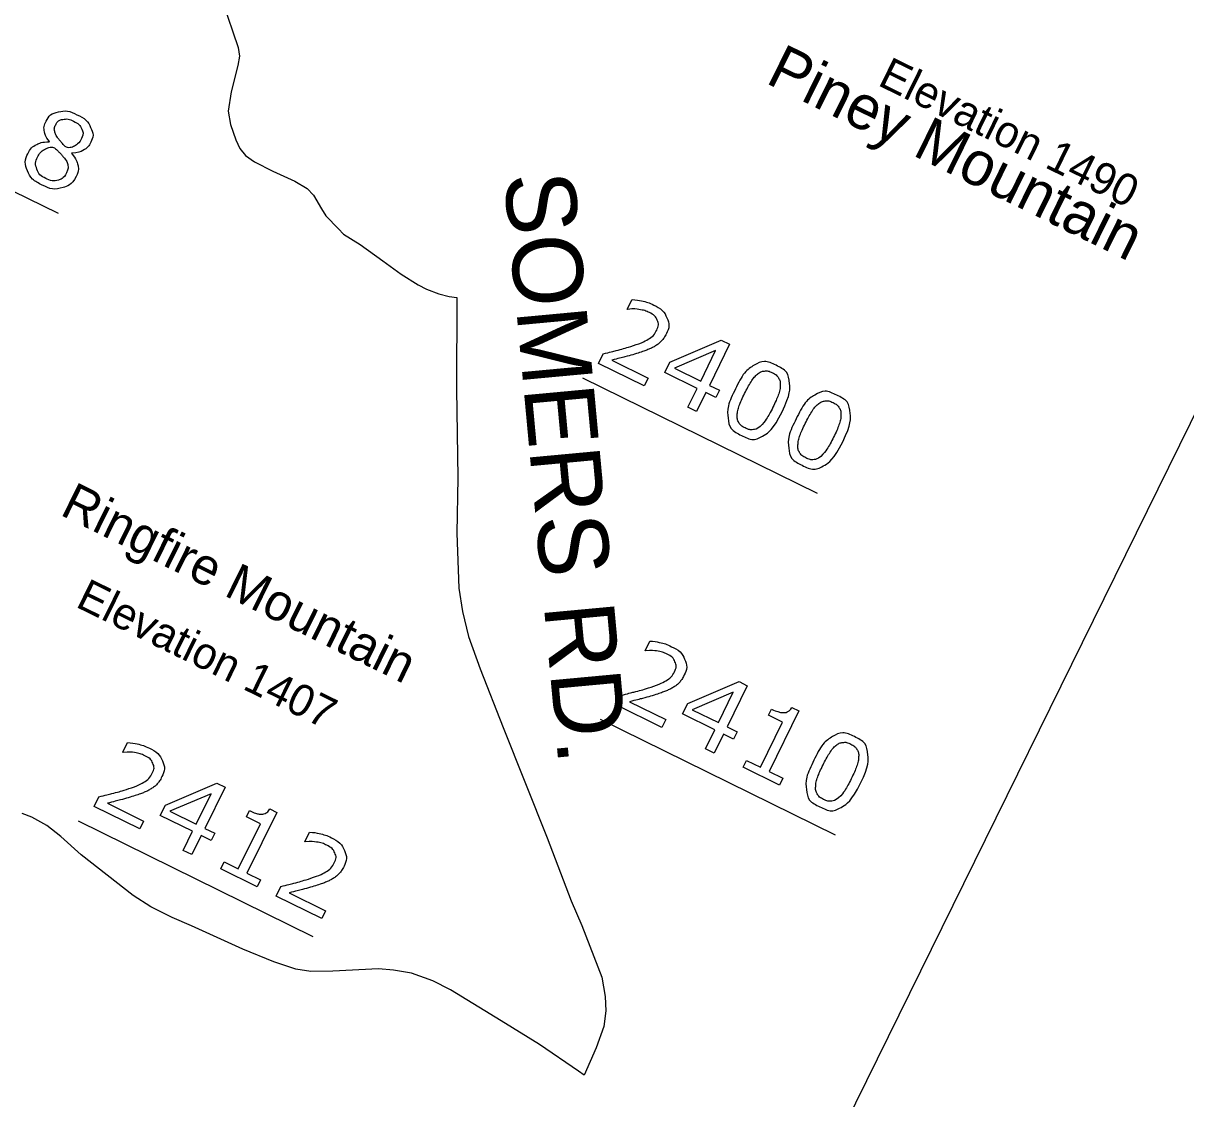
# Model space of a CAD drawing. Extents: x 1428128 to 1430390, y 857947 to 859822.
# Drawn here: x 1429189.4 to 1429305.6, y 859217.9 to 859325.3 of the extents above; entities that cross this region are included whole.
import ezdxf

# ---------------------------------------------------------------- set-up
doc = ezdxf.new("R2010")
doc.units = 0
doc.layers.add('Old_Level_1', color=7, linetype='Continuous')
doc.layers.add('Sheet Title CELL', color=7, linetype='Continuous')

msp = doc.modelspace()

# ---------------------------------------------------------------- linework, layer by layer
at = {"layer": 'Old_Level_1'}
for p, q in [((1429169.37, 859317.89), (1429192.89, 859306.32)), ((1429245.28, 859289.88), (1429268.74, 859278.34)), ((1429247.05, 859255.76), (1429270.52, 859244.22)), ((1429194.88, 859245.62), (1429218.35, 859234.07))]:
    msp.add_line(p, q, dxfattribs=at)
for points in [[(1429192, 859313.45), (1429192.02, 859313.48)], [(1429194.23, 859312.34), (1429194.22, 859312.31)], [(1429249.81, 859296.72), (1429249.76, 859296.75), (1429250.23, 859297.69)], [(1429258.6, 859287.91), (1429257.6, 859288.41), (1429256.67, 859286.51), (1429255.8, 859286.94), (1429256.73, 859288.83), (1429253.51, 859290.42), (1429254.02, 859291.46), (1429259.15, 859293.65), (1429259.98, 859293.24), (1429257.96, 859289.13), (1429258.96, 859288.64), (1429258.6, 859287.91)], [(1429251.45, 859289.08), (1429246.89, 859291.32), (1429247.36, 859292.27)], [(1429257.09, 859289.56), (1429258.58, 859292.6), (1429254.48, 859290.84), (1429257.09, 859289.56)], [(1429248.21, 859291.64), (1429251.83, 859289.86), (1429251.45, 859289.08)], [(1429251.58, 859262.6), (1429251.53, 859262.62), (1429252, 859263.57)], [(1429260.37, 859253.79), (1429259.37, 859254.29), (1429258.44, 859252.39), (1429257.57, 859252.82), (1429258.5, 859254.71), (1429255.28, 859256.3), (1429255.79, 859257.34), (1429260.92, 859259.53), (1429261.75, 859259.12), (1429259.73, 859255.01), (1429260.73, 859254.52), (1429260.37, 859253.79)], [(1429253.22, 859254.96), (1429248.66, 859257.2), (1429249.13, 859258.15)], [(1429258.86, 859255.44), (1429260.35, 859258.48), (1429256.25, 859256.72), (1429258.86, 859255.44)], [(1429249.98, 859257.52), (1429253.6, 859255.74), (1429253.22, 859254.96)], [(1429266.21, 859256.95), (1429266.91, 859256.61), (1429263.93, 859250.54), (1429265.3, 859249.87), (1429264.96, 859249.18)], [(1429264.96, 859249.18), (1429261.32, 859250.97), (1429261.66, 859251.66), (1429263.06, 859250.97), (1429265.28, 859255.48), (1429263.88, 859256.17), (1429264.18, 859256.78)], [(1429199.4, 859252.46), (1429199.36, 859252.48), (1429199.83, 859253.43)], [(1429208.19, 859243.65), (1429207.19, 859244.14), (1429206.26, 859242.24), (1429205.39, 859242.67), (1429206.33, 859244.57), (1429203.1, 859246.15), (1429203.61, 859247.19), (1429208.74, 859249.38), (1429209.57, 859248.97), (1429207.55, 859244.86), (1429208.55, 859244.37), (1429208.19, 859243.65)], [(1429201.05, 859244.81), (1429196.49, 859247.05), (1429196.95, 859248.01)], [(1429206.68, 859245.29), (1429208.18, 859248.33), (1429204.07, 859246.58), (1429206.68, 859245.29)], [(1429197.81, 859247.37), (1429201.43, 859245.59), (1429201.05, 859244.81)], [(1429212.79, 859239.03), (1429209.14, 859240.83), (1429209.48, 859241.51), (1429210.88, 859240.82), (1429213.1, 859245.33), (1429211.7, 859246.02), (1429212, 859246.64)], [(1429214.03, 859246.81), (1429214.74, 859246.46), (1429211.75, 859240.4), (1429213.12, 859239.72), (1429212.79, 859239.03)], [(1429217.59, 859243.51), (1429217.55, 859243.53), (1429218.01, 859244.48)], [(1429219.23, 859235.86), (1429214.67, 859238.1), (1429215.14, 859239.06)], [(1429215.99, 859238.42), (1429219.62, 859236.64), (1429219.23, 859235.86)]]:
    msp.add_lwpolyline(points, dxfattribs=at)
for points in [[(1429192.02, 859313.48), (1429191.61, 859314.03), (1429191.52, 859314.5), (1429191.43, 859314.98), (1429191.69, 859315.49), (1429192.06, 859316.25), (1429192.93, 859316.45), (1429193.81, 859316.65), (1429194.77, 859316.17), (1429195.78, 859315.68), (1429196.14, 859314.9), (1429196.5, 859314.12), (1429196.14, 859313.37), (1429195.91, 859312.92), (1429195.41, 859312.62), (1429194.91, 859312.32), (1429194.23, 859312.34)], [(1429195.24, 859313.8), (1429195.48, 859314.29), (1429195.25, 859314.76), (1429195.02, 859315.23), (1429194.44, 859315.51), (1429193.87, 859315.79), (1429193.37, 859315.7), (1429192.87, 859315.61), (1429192.64, 859315.15), (1429192.48, 859314.82), (1429192.55, 859314.5), (1429192.62, 859314.17), (1429192.9, 859313.8), (1429193.02, 859313.64), (1429193.27, 859313.35), (1429193.52, 859313.06), (1429193.78, 859312.83), (1429194.38, 859312.91), (1429194.71, 859313.15), (1429195.04, 859313.38), (1429195.24, 859313.8)], [(1429194.7, 859309.99), (1429194.27, 859309.12), (1429193.3, 859308.87), (1429192.34, 859308.63), (1429191.31, 859309.14), (1429190.21, 859309.68), (1429189.84, 859310.56), (1429189.47, 859311.44), (1429189.9, 859312.33), (1429190.18, 859312.89), (1429190.73, 859313.18), (1429191.28, 859313.47), (1429192, 859313.45)], [(1429193.73, 859310.36), (1429193.93, 859310.78), (1429193.87, 859311.12), (1429193.81, 859311.46), (1429193.4, 859311.97), (1429193.24, 859312.18), (1429193.03, 859312.39), (1429192.82, 859312.6), (1429192.47, 859312.96), (1429191.96, 859312.94), (1429191.52, 859312.68), (1429191.09, 859312.42), (1429190.85, 859311.94), (1429190.55, 859311.33), (1429190.78, 859310.73), (1429191, 859310.12), (1429191.65, 859309.81), (1429192.31, 859309.48), (1429192.87, 859309.63), (1429193.44, 859309.77), (1429193.73, 859310.36)], [(1429194.22, 859312.31), (1429194.72, 859311.73), (1429194.86, 859311.17), (1429195, 859310.6), (1429194.7, 859309.99)], [(1429250.23, 859297.69), (1429250.63, 859297.69), (1429251.23, 859297.56), (1429251.83, 859297.43), (1429252.33, 859297.18), (1429253.37, 859296.67), (1429253.71, 859295.88), (1429254.05, 859295.09), (1429253.63, 859294.24), (1429253.45, 859293.86), (1429253.18, 859293.57), (1429252.92, 859293.29), (1429252.59, 859293.08), (1429252.27, 859292.89), (1429251.9, 859292.74), (1429251.53, 859292.58), (1429251.03, 859292.42), (1429250.31, 859292.18), (1429249.58, 859291.99), (1429248.84, 859291.8), (1429248.21, 859291.64)], [(1429247.36, 859292.27), (1429248.03, 859292.45), (1429248.71, 859292.62), (1429249.39, 859292.79), (1429250, 859292.99), (1429251.28, 859293.4), (1429251.85, 859293.74), (1429252.41, 859294.07), (1429252.7, 859294.65), (1429252.95, 859295.17), (1429252.75, 859295.64), (1429252.55, 859296.1), (1429251.93, 859296.41), (1429251.52, 859296.61), (1429250.97, 859296.7), (1429250.41, 859296.8), (1429249.81, 859296.72)], [(1429265.22, 859286.49), (1429264.33, 859284.67), (1429263.34, 859284.1), (1429262.36, 859283.53), (1429261.17, 859284.12), (1429259.96, 859284.72), (1429259.82, 859285.85), (1429259.69, 859286.98), (1429260.56, 859288.77), (1429261.45, 859290.56), (1429262.44, 859291.14), (1429263.42, 859291.72), (1429264.62, 859291.13), (1429265.83, 859290.54), (1429265.96, 859289.39), (1429266.09, 859288.25), (1429265.22, 859286.49)], [(1429263.02, 859285.02), (1429263.36, 859285.31), (1429263.66, 859285.77), (1429263.96, 859286.24), (1429264.3, 859286.94), (1429264.64, 859287.63), (1429264.84, 859288.16), (1429265.03, 859288.7), (1429265.04, 859289.13), (1429265.05, 859289.55), (1429264.87, 859289.87), (1429264.68, 859290.18), (1429264.25, 859290.39), (1429263.83, 859290.6), (1429263.46, 859290.56), (1429263.1, 859290.52), (1429262.76, 859290.24), (1429262.44, 859289.98), (1429262.12, 859289.47), (1429261.8, 859288.96), (1429261.48, 859288.32), (1429261.13, 859287.61), (1429260.95, 859287.11), (1429260.77, 859286.61), (1429260.74, 859286.15), (1429260.72, 859285.73), (1429260.9, 859285.41), (1429261.08, 859285.09), (1429261.54, 859284.87), (1429261.96, 859284.66), (1429262.33, 859284.7), (1429262.69, 859284.74), (1429263.02, 859285.02)], [(1429271.29, 859283.5), (1429270.39, 859281.69), (1429269.41, 859281.12), (1429268.42, 859280.55), (1429267.23, 859281.14), (1429266.02, 859281.73), (1429265.89, 859282.87), (1429265.75, 859284), (1429266.63, 859285.78), (1429267.51, 859287.58), (1429268.5, 859288.16), (1429269.49, 859288.74), (1429270.68, 859288.15), (1429271.89, 859287.56), (1429272.02, 859286.41), (1429272.15, 859285.26), (1429271.29, 859283.5)], [(1429269.09, 859282.03), (1429269.42, 859282.32), (1429269.72, 859282.79), (1429270.02, 859283.26), (1429270.37, 859283.95), (1429270.71, 859284.64), (1429270.9, 859285.18), (1429271.09, 859285.71), (1429271.1, 859286.14), (1429271.12, 859286.57), (1429270.93, 859286.88), (1429270.74, 859287.19), (1429270.31, 859287.4), (1429269.89, 859287.61), (1429269.53, 859287.57), (1429269.16, 859287.53), (1429268.82, 859287.26), (1429268.5, 859287), (1429268.18, 859286.49), (1429267.86, 859285.98), (1429267.55, 859285.33), (1429267.2, 859284.63), (1429267.01, 859284.13), (1429266.83, 859283.63), (1429266.81, 859283.17), (1429266.78, 859282.75), (1429266.96, 859282.43), (1429267.15, 859282.11), (1429267.6, 859281.88), (1429268.02, 859281.67), (1429268.39, 859281.71), (1429268.76, 859281.75), (1429269.09, 859282.03)], [(1429249.13, 859258.15), (1429249.81, 859258.33), (1429250.48, 859258.5), (1429251.16, 859258.67), (1429251.77, 859258.87), (1429253.05, 859259.28), (1429253.62, 859259.62), (1429254.18, 859259.95), (1429254.47, 859260.53), (1429254.72, 859261.05), (1429254.52, 859261.52), (1429254.32, 859261.98), (1429253.7, 859262.29), (1429253.29, 859262.49), (1429252.74, 859262.58), (1429252.18, 859262.67), (1429251.58, 859262.6)], [(1429252, 859263.57), (1429252.4, 859263.57), (1429253, 859263.44), (1429253.6, 859263.31), (1429254.1, 859263.06), (1429255.14, 859262.55), (1429255.48, 859261.76), (1429255.83, 859260.97), (1429255.41, 859260.12), (1429255.22, 859259.73), (1429254.96, 859259.45), (1429254.7, 859259.17), (1429254.36, 859258.96), (1429254.04, 859258.77), (1429253.67, 859258.61), (1429253.3, 859258.46), (1429252.8, 859258.3), (1429252.08, 859258.06), (1429251.35, 859257.87), (1429250.62, 859257.68), (1429249.98, 859257.52)], [(1429264.18, 859256.78), (1429264.46, 859256.64), (1429264.81, 859256.53), (1429265.16, 859256.42), (1429265.37, 859256.43), (1429265.64, 859256.44), (1429265.84, 859256.55), (1429266.05, 859256.67), (1429266.21, 859256.95)], [(1429199.83, 859253.43), (1429200.22, 859253.43), (1429200.83, 859253.29), (1429201.43, 859253.16), (1429201.93, 859252.91), (1429202.96, 859252.4), (1429203.31, 859251.61), (1429203.65, 859250.83), (1429203.23, 859249.97), (1429203.04, 859249.59), (1429202.78, 859249.3), (1429202.52, 859249.02), (1429202.18, 859248.82), (1429201.87, 859248.62), (1429201.5, 859248.47), (1429201.13, 859248.31), (1429200.63, 859248.15), (1429199.91, 859247.92), (1429199.17, 859247.72), (1429198.44, 859247.53), (1429197.81, 859247.37)], [(1429273.06, 859249.38), (1429272.16, 859247.57), (1429271.18, 859247), (1429270.19, 859246.43), (1429269, 859247.01), (1429267.79, 859247.61), (1429267.66, 859248.74), (1429267.52, 859249.88), (1429268.4, 859251.66), (1429269.28, 859253.46), (1429270.27, 859254.04), (1429271.26, 859254.62), (1429272.45, 859254.03), (1429273.66, 859253.43), (1429273.79, 859252.29), (1429273.92, 859251.14), (1429273.06, 859249.38)], [(1429270.86, 859247.91), (1429271.2, 859248.2), (1429271.5, 859248.67), (1429271.8, 859249.14), (1429272.14, 859249.83), (1429272.48, 859250.52), (1429272.67, 859251.06), (1429272.86, 859251.59), (1429272.87, 859252.02), (1429272.89, 859252.45), (1429272.7, 859252.76), (1429272.51, 859253.07), (1429272.09, 859253.28), (1429271.66, 859253.49), (1429271.3, 859253.45), (1429270.93, 859253.41), (1429270.59, 859253.13), (1429270.28, 859252.88), (1429269.95, 859252.36), (1429269.63, 859251.85), (1429269.32, 859251.21), (1429268.97, 859250.51), (1429268.78, 859250.01), (1429268.6, 859249.51), (1429268.58, 859249.05), (1429268.55, 859248.62), (1429268.74, 859248.3), (1429268.92, 859247.98), (1429269.37, 859247.76), (1429269.79, 859247.55), (1429270.16, 859247.59), (1429270.53, 859247.63), (1429270.86, 859247.91)], [(1429196.95, 859248.01), (1429197.63, 859248.18), (1429198.31, 859248.35), (1429198.99, 859248.52), (1429199.6, 859248.72), (1429200.88, 859249.13), (1429201.44, 859249.47), (1429202.01, 859249.81), (1429202.29, 859250.38), (1429202.55, 859250.9), (1429202.35, 859251.37), (1429202.15, 859251.84), (1429201.52, 859252.14), (1429201.11, 859252.34), (1429200.56, 859252.44), (1429200.01, 859252.53), (1429199.4, 859252.46)], [(1429212, 859246.64), (1429212.29, 859246.5), (1429212.64, 859246.38), (1429212.99, 859246.27), (1429213.2, 859246.28), (1429213.46, 859246.29), (1429213.67, 859246.41), (1429213.87, 859246.52), (1429214.03, 859246.81)], [(1429218.01, 859244.48), (1429218.41, 859244.48), (1429219.01, 859244.34), (1429219.61, 859244.21), (1429220.12, 859243.96), (1429221.15, 859243.45), (1429221.5, 859242.66), (1429221.84, 859241.88), (1429221.42, 859241.02), (1429221.23, 859240.64), (1429220.97, 859240.35), (1429220.71, 859240.07), (1429220.37, 859239.87), (1429220.06, 859239.67), (1429219.69, 859239.52), (1429219.32, 859239.36), (1429218.81, 859239.2), (1429218.1, 859238.97), (1429217.36, 859238.77), (1429216.63, 859238.58), (1429215.99, 859238.42)], [(1429215.14, 859239.06), (1429215.82, 859239.23), (1429216.5, 859239.4), (1429217.17, 859239.57), (1429217.78, 859239.77), (1429219.07, 859240.18), (1429219.63, 859240.52), (1429220.2, 859240.86), (1429220.48, 859241.43), (1429220.74, 859241.95), (1429220.54, 859242.42), (1429220.33, 859242.89), (1429219.71, 859243.19), (1429219.3, 859243.4), (1429218.75, 859243.49), (1429218.2, 859243.58), (1429217.59, 859243.51)]]:
    msp.add_open_spline(points, degree=3, dxfattribs=at)
at = {"layer": 'Sheet Title CELL'}
msp.add_line((1429358.43, 859391.92), (1429217.15, 859104.79), dxfattribs=at)
for points in [[(1429209.33, 859327.48), (1429210.88, 859322.87), (1429211.02, 859322.02), (1429210.85, 859321.1), (1429210.18, 859318.46), (1429209.87, 859316.53), (1429210.1, 859315.2), (1429210.66, 859313.67), (1429211.04, 859312.8), (1429211.61, 859312.11), (1429212.5, 859311.45), (1429214.33, 859310.52), (1429216.55, 859309.52), (1429217.79, 859308.79), (1429218.41, 859308.14), (1429219.19, 859306.76), (1429219.63, 859306.07), (1429220.92, 859304.75), (1429221.42, 859304.25), (1429223.06, 859303.19), (1429225.33, 859301.58), (1429227.16, 859300.24), (1429228.85, 859299.16), (1429229.7, 859298.74), (1429230.94, 859298.26), (1429231.97, 859298), (1429232.72, 859297.92)], [(1429232.72, 859297.92), (1429232.68, 859288.74), (1429232.82, 859279.9), (1429232.72, 859274.37), (1429232.93, 859268.88), (1429233.3, 859266.52), (1429233.89, 859264.05), (1429235.06, 859260.81), (1429237.34, 859254.96), (1429241.76, 859243.92), (1429244.16, 859237.63), (1429245.2, 859235.15), (1429247.2, 859229.99), (1429247.56, 859228.07), (1429247.61, 859226.62), (1429247.4, 859225.07), (1429246.64, 859222.94), (1429245.44, 859220.21)], [(1429245.44, 859220.21), (1429244.89, 859220.61), (1429241, 859223.26), (1429237.15, 859225.62), (1429232.11, 859228.74), (1429230.33, 859229.64), (1429228.2, 859230.4), (1429226.41, 859230.7), (1429224.89, 859230.83), (1429220.35, 859230.6), (1429218.14, 859230.58), (1429216.64, 859230.81), (1429214.43, 859231.54), (1429211.34, 859232.81), (1429206.22, 859235.13), (1429204.28, 859235.95), (1429202.14, 859237.01), (1429200.39, 859238.17), (1429195.21, 859242.22), (1429193.15, 859244.05), (1429191.77, 859245.14), (1429190.27, 859245.98), (1429189.29, 859246.36)]]:
    msp.add_lwpolyline(points, dxfattribs=at)

# ---------------------------------------------------------------- texts
at = {"layer": 'Old_Level_1'}
for s, height, rotation, p in [('Piney Mountain', 4.4, 333.8001, (1429263.46, 859319.39)), ('Elevation 1490', 3.1667, 333.8001, (1429274.67, 859319.17)), ('SOMERS RD.', 7, 275.3061, (1429237.42, 859310.14)), ('Ringfire Mountain', 3.6667, 333.8001, (1429192.97, 859276.25)), ('Elevation 1407', 3.1667, 333.8001, (1429194.53, 859267.06))]:
    msp.add_text(s, height=height, rotation=rotation, dxfattribs=at).set_placement(p)

doc.saveas('drawing.dxf')
